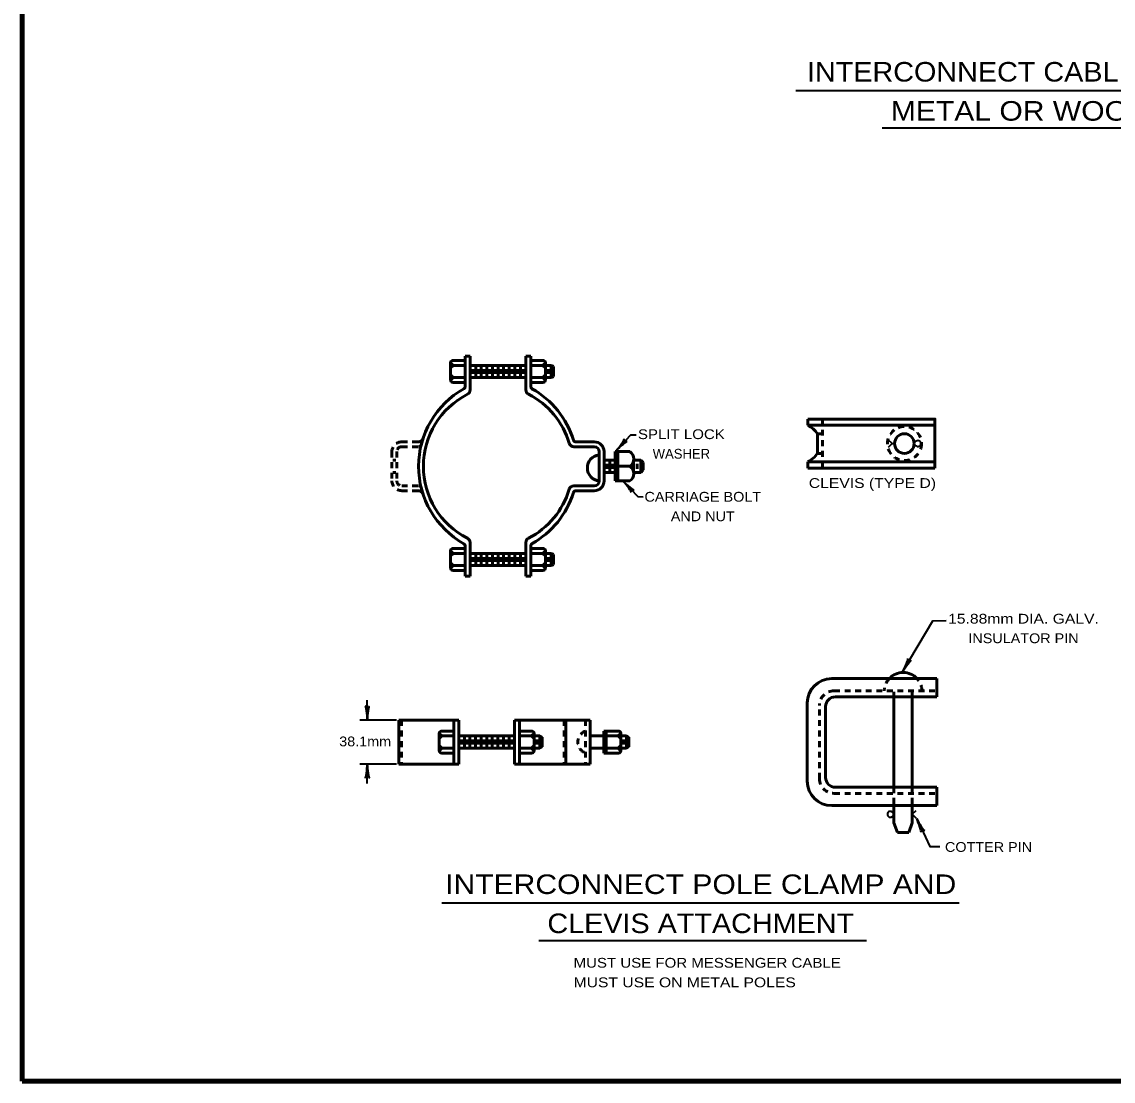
# Model space of a CAD drawing. Extents: x -421 to 434, y -46 to 498.
# Drawn here: x -364.1 to -96.1, y -34.2 to 225.9 of the extents above; entities that cross this region are included whole.
import ezdxf
from ezdxf.enums import TextEntityAlignment as Align

# ---------------------------------------------------------------- set-up
doc = ezdxf.new("R2010")
doc.units = 0
doc.header["$LTSCALE"] = 0.96
doc.linetypes.add('MEDIUM_DASHED', pattern=[4.5, 3, -1.5])
doc.linetypes.add('SHORT_DASHED', pattern=[2.7, 1.5, -1.2])
doc.layers.add('1', color=7, linetype='Continuous', lineweight=53)

msp = doc.modelspace()

# ---------------------------------------------------------------- linework, layer by layer
at = {"layer": '1', "lineweight": 40}
for p, q in [((-174.0904, 209.0297), (-37.3404, 209.0297)), ((-152.8823, 199.8058), (-57.4422, 199.8058)), ((-261.0137, 9.5761), (-133.9247, 9.5761)), ((-237.1632, 0.3522), (-156.753, 0.3522))]:
    msp.add_line(p, q, dxfattribs=at)
at = {"layer": '1'}
for p, q in [((-258.2165, 141.5306), (-258.8529, 142.167)), ((-258.8529, 142.1306), (-258.8529, 137.9306)), ((-258.2529, 142.7306), (-255.2529, 142.7306)), ((-255.2537, 136.3081), (-255.2537, 143.7531)), ((-255.2537, 143.7531), (-254.0537, 143.7531)), ((-254.0537, 135.5018), (-254.0537, 143.7531)), ((-240.3511, 135.5018), (-240.3511, 143.7531)), ((-240.3511, 143.7531), (-239.1511, 143.7531)), ((-239.1511, 136.3081), (-239.1511, 143.7531)), ((-236.1511, 142.7306), (-239.1511, 142.7306)), ((-236.1875, 141.5306), (-235.5511, 142.167)), ((-235.5511, 142.1306), (-235.5511, 137.9306)), ((-258.2165, 141.5306), (-258.8529, 140.8942)), ((-258.2165, 141.5306), (-255.2529, 141.5306)), ((-240.3511, 141.5306), (-254.0537, 141.5306)), ((-253.3685, 139.4306), (-253.3685, 140.6306)), ((-252.6833, 138.5306), (-252.6833, 141.5306)), ((-251.9981, 139.4306), (-251.9981, 140.6306)), ((-251.3129, 138.5306), (-251.3129, 141.5306)), ((-250.6277, 139.4306), (-250.6277, 140.6306)), ((-249.9425, 138.5306), (-249.9425, 141.5306)), ((-249.2573, 139.4306), (-249.2573, 140.6306)), ((-248.5721, 138.5306), (-248.5721, 141.5306)), ((-247.8869, 139.4306), (-247.8869, 140.6306)), ((-247.2017, 138.5306), (-247.2017, 141.5306)), ((-246.5165, 139.4306), (-246.5165, 140.6306)), ((-245.8313, 138.5306), (-245.8313, 141.5306)), ((-245.1461, 139.4306), (-245.1461, 140.6306)), ((-244.4609, 138.5306), (-244.4609, 141.5306)), ((-243.7757, 139.4306), (-243.7757, 140.6306)), ((-243.0905, 138.5306), (-243.0905, 141.5306)), ((-242.4053, 139.4306), (-242.4053, 140.6306)), ((-241.7201, 138.5306), (-241.7201, 141.5306)), ((-241.0349, 139.4306), (-241.0349, 140.6306)), ((-236.1875, 141.5306), (-239.1511, 141.5306)), ((-236.1875, 141.5306), (-235.5511, 140.8942)), ((-234.1807, 141.5306), (-235.5511, 141.5306)), ((-234.8708, 139.4306), (-234.8708, 140.6306)), ((-234.1807, 141.5306), (-234.1807, 138.5306)), ((-234.1807, 141.5306), (-233.5807, 141.2306)), ((-233.5807, 141.2306), (-233.5807, 138.8306)), ((-258.2165, 138.5306), (-258.8529, 139.167)), ((-258.2165, 138.5306), (-258.8529, 137.8942)), ((-258.2529, 137.3306), (-255.2529, 137.3306)), ((-258.2165, 138.5306), (-255.2529, 138.5306)), ((-240.3511, 138.5306), (-254.0537, 138.5306)), ((-236.1875, 138.5306), (-239.1511, 138.5306)), ((-236.1511, 137.3306), (-239.1511, 137.3306)), ((-236.1875, 138.5306), (-235.5511, 139.167)), ((-236.1875, 138.5306), (-235.5511, 137.8942)), ((-234.1807, 138.5306), (-235.5511, 138.5306)), ((-234.1807, 138.5306), (-233.5807, 138.8306)), ((-171.1344, 128.3214), (-171.1344, 126.8214)), ((-171.1344, 126.8214), (-139.9344, 126.8214)), ((-168.7344, 124.7214), (-168.7344, 119.9214)), ((-168.7344, 124.7214), (-167.5344, 124.7214)), ((-223.5511, 121.5531), (-228.5593, 121.5531)), ((-223.5511, 122.7531), (-228.0922, 122.7531)), ((-273.0137, 118.2531), (-272.2937, 118.2531)), ((-222.3511, 120.3531), (-222.3511, 113.1531)), ((-221.1511, 120.3531), (-221.1511, 113.1531)), ((-221.1511, 118.2531), (-218.4103, 118.2531)), ((-219.7807, 118.2531), (-219.7807, 115.2531)), ((-218.4103, 120.3531), (-218.4103, 113.1531)), ((-218.4103, 120.3531), (-214.8103, 120.3531)), ((-217.8103, 120.3531), (-217.8103, 113.1531)), ((-213.9008, 118.2531), (-212.1511, 118.2531)), ((-213.9008, 118.2531), (-213.9008, 115.2531)), ((-212.1511, 118.2531), (-212.1511, 115.2531)), ((-212.1511, 118.2531), (-211.5511, 117.6531)), ((-168.7344, 119.9214), (-167.5344, 119.9214)), ((-273.0137, 115.2531), (-272.2937, 115.2531)), ((-221.1511, 115.2531), (-218.4103, 115.2531)), ((-220.4659, 117.3531), (-220.4659, 116.1531)), ((-219.0955, 117.3531), (-219.0955, 116.1531)), ((-217.8103, 116.7531), (-214.8103, 116.7531)), ((-213.9008, 115.2531), (-212.1511, 115.2531)), ((-213.0297, 117.3531), (-213.0297, 116.1531)), ((-211.5511, 115.8531), (-212.1511, 115.2531)), ((-211.5511, 117.6531), (-211.5511, 115.8531)), ((-171.1344, 117.8214), (-139.9344, 117.8214)), ((-171.1344, 117.8214), (-171.1344, 116.3214)), ((-171.1344, 116.3214), (-139.9344, 116.3214)), ((-218.4103, 113.1531), (-214.8103, 113.1531)), ((-223.5511, 111.9531), (-228.5681, 111.9531)), ((-223.5511, 110.7531), (-228.1014, 110.7531)), ((-258.2529, 96.5787), (-255.2529, 96.5787)), ((-255.2537, 97.1981), (-255.2537, 89.7531)), ((-254.0537, 98.0044), (-254.0537, 89.7531)), ((-240.3511, 98.0342), (-240.3511, 89.7531)), ((-239.1511, 97.2344), (-239.1511, 89.7531)), ((-236.1511, 96.5787), (-239.1511, 96.5787)), ((-258.2165, 95.3787), (-258.8529, 96.0151)), ((-258.8529, 95.9787), (-258.8529, 91.7787)), ((-258.2165, 95.3787), (-258.8529, 94.7423)), ((-258.2165, 95.3787), (-255.2529, 95.3787)), ((-240.3511, 95.3787), (-254.0537, 95.3787)), ((-253.3685, 93.2787), (-253.3685, 94.4787)), ((-252.6833, 92.3787), (-252.6833, 95.3787)), ((-251.9981, 93.2787), (-251.9981, 94.4787)), ((-251.3129, 92.3787), (-251.3129, 95.3787)), ((-250.6277, 93.2787), (-250.6277, 94.4787)), ((-249.9425, 92.3787), (-249.9425, 95.3787)), ((-249.2573, 93.2787), (-249.2573, 94.4787)), ((-248.5721, 92.3787), (-248.5721, 95.3787)), ((-247.8869, 93.2787), (-247.8869, 94.4787)), ((-247.2017, 92.3787), (-247.2017, 95.3787)), ((-246.5165, 93.2787), (-246.5165, 94.4787)), ((-245.8313, 92.3787), (-245.8313, 95.3787)), ((-245.1461, 93.2787), (-245.1461, 94.4787)), ((-244.4609, 92.3787), (-244.4609, 95.3787)), ((-243.7757, 93.2787), (-243.7757, 94.4787)), ((-243.0905, 92.3787), (-243.0905, 95.3787)), ((-242.4053, 93.2787), (-242.4053, 94.4787)), ((-241.7201, 92.3787), (-241.7201, 95.3787)), ((-241.0349, 93.2787), (-241.0349, 94.4787)), ((-236.1875, 95.3787), (-239.1511, 95.3787)), ((-236.1875, 95.3787), (-235.5511, 96.0151)), ((-236.1875, 95.3787), (-235.5511, 94.7423)), ((-235.5511, 95.9787), (-235.5511, 91.7787)), ((-234.1807, 95.3787), (-235.5511, 95.3787)), ((-234.8708, 93.2787), (-234.8708, 94.4787)), ((-234.1807, 95.3787), (-234.1807, 92.3787)), ((-234.1807, 95.3787), (-233.5807, 95.0787)), ((-233.5807, 95.0787), (-233.5807, 92.6787)), ((-258.2165, 92.3787), (-258.8529, 93.0151)), ((-258.2165, 92.3787), (-258.8529, 91.7423)), ((-258.2529, 91.1787), (-255.2529, 91.1787)), ((-258.2165, 92.3787), (-255.2529, 92.3787)), ((-240.3511, 92.3787), (-254.0537, 92.3787)), ((-236.1875, 92.3787), (-239.1511, 92.3787)), ((-236.1511, 91.1787), (-239.1511, 91.1787)), ((-236.1875, 92.3787), (-235.5511, 93.0151)), ((-236.1875, 92.3787), (-235.5511, 91.7423)), ((-234.1807, 92.3787), (-235.5511, 92.3787)), ((-234.1807, 92.3787), (-233.5807, 92.6787)), ((-255.2537, 89.7531), (-254.0537, 89.7531)), ((-240.3511, 89.7531), (-239.1511, 89.7531)), ((-165.264, 64.647), (-139.464, 64.647)), ((-139.464, 64.647), (-139.464, 60.147)), ((-164.364, 60.147), (-139.464, 60.147)), ((-149.964, 60.147), (-149.964, 37.947)), ((-145.464, 60.147), (-145.464, 37.947)), ((-171.264, 39.447), (-171.264, 58.647)), ((-166.764, 40.347), (-166.764, 57.747)), ((-258.0362, 54.447), (-271.5362, 54.447)), ((-271.5362, 54.447), (-271.5362, 43.647)), ((-258.0362, 54.447), (-258.0362, 43.647)), ((-258.0362, 54.447), (-256.8362, 54.447)), ((-256.8362, 54.447), (-256.8362, 43.647)), ((-243.1344, 54.447), (-243.1344, 43.647)), ((-243.1344, 54.447), (-241.9344, 54.447)), ((-241.9344, 54.447), (-241.9344, 43.647)), ((-241.9344, 54.447), (-224.5344, 54.447)), ((-230.5344, 54.447), (-230.5344, 43.647)), ((-224.5344, 54.447), (-224.5344, 43.647)), ((-260.9998, 50.547), (-261.6362, 51.1834)), ((-261.6362, 51.147), (-261.6362, 46.947)), ((-261.0362, 51.747), (-258.0362, 51.747)), ((-238.9344, 51.747), (-241.9344, 51.747)), ((-238.9708, 50.547), (-238.3344, 51.1834)), ((-238.3344, 51.147), (-238.3344, 46.947)), ((-217.6344, 51.747), (-221.2344, 51.747)), ((-221.2344, 51.747), (-221.2344, 46.347)), ((-220.6344, 51.747), (-220.6344, 46.347)), ((-217.6708, 50.547), (-217.0344, 51.1834)), ((-217.0344, 51.147), (-217.0344, 46.947)), ((-260.9998, 50.547), (-261.6362, 49.9106)), ((-260.9998, 50.547), (-258.0362, 50.547)), ((-243.1344, 50.547), (-256.837, 50.547)), ((-256.1518, 48.447), (-256.1518, 49.647)), ((-255.4666, 47.547), (-255.4666, 50.547)), ((-254.7814, 48.447), (-254.7814, 49.647)), ((-254.0962, 47.547), (-254.0962, 50.547)), ((-253.411, 48.447), (-253.411, 49.647)), ((-252.7258, 47.547), (-252.7258, 50.547)), ((-252.0406, 48.447), (-252.0406, 49.647)), ((-251.3554, 47.547), (-251.3554, 50.547)), ((-250.6702, 48.447), (-250.6702, 49.647)), ((-249.985, 47.547), (-249.985, 50.547)), ((-249.2998, 48.447), (-249.2998, 49.647)), ((-248.6146, 47.547), (-248.6146, 50.547)), ((-247.9294, 48.447), (-247.9294, 49.647)), ((-247.2442, 47.547), (-247.2442, 50.547)), ((-246.559, 48.447), (-246.559, 49.647)), ((-245.8738, 47.547), (-245.8738, 50.547)), ((-245.1886, 48.447), (-245.1886, 49.647)), ((-244.5034, 47.547), (-244.5034, 50.547)), ((-243.8182, 48.447), (-243.8182, 49.647)), ((-238.9708, 50.547), (-241.9344, 50.547)), ((-238.9708, 50.547), (-238.3344, 49.9106)), ((-236.964, 50.547), (-238.3344, 50.547)), ((-237.6541, 48.447), (-237.6541, 49.647)), ((-236.964, 50.547), (-236.964, 47.547)), ((-236.964, 50.547), (-236.364, 50.247)), ((-236.364, 50.247), (-236.364, 47.847)), ((-224.5344, 50.547), (-221.2344, 50.547)), ((-217.6708, 50.547), (-220.6344, 50.547)), ((-217.6708, 50.547), (-217.0344, 49.9106)), ((-215.664, 50.547), (-217.0344, 50.547)), ((-216.3541, 48.447), (-216.3541, 49.647)), ((-215.664, 50.547), (-215.664, 47.547)), ((-215.664, 50.547), (-215.064, 50.247)), ((-215.064, 50.247), (-215.064, 47.847)), ((-260.9998, 47.547), (-261.6362, 48.1834)), ((-260.9998, 47.547), (-261.6362, 46.9106)), ((-261.0362, 46.347), (-258.0362, 46.347)), ((-260.9998, 47.547), (-258.0362, 47.547)), ((-243.1344, 47.547), (-256.837, 47.547)), ((-238.9708, 47.547), (-241.9344, 47.547)), ((-238.9344, 46.347), (-241.9344, 46.347)), ((-238.9708, 47.547), (-238.3344, 48.1834)), ((-238.9708, 47.547), (-238.3344, 46.9106)), ((-236.964, 47.547), (-238.3344, 47.547)), ((-236.964, 47.547), (-236.364, 47.847)), ((-224.5344, 47.547), (-221.2344, 47.547)), ((-217.6344, 46.347), (-221.2344, 46.347)), ((-217.6708, 47.547), (-220.6344, 47.547)), ((-217.6708, 47.547), (-217.0344, 48.1834)), ((-217.6708, 47.547), (-217.0344, 46.9106)), ((-215.664, 47.547), (-217.0344, 47.547)), ((-215.664, 47.547), (-215.064, 47.847)), ((-258.0362, 43.647), (-271.5362, 43.647)), ((-258.0362, 43.647), (-256.8362, 43.647)), ((-243.1344, 43.647), (-241.9344, 43.647)), ((-241.9344, 43.647), (-224.5344, 43.647)), ((-164.364, 37.947), (-139.464, 37.947)), ((-139.464, 37.947), (-139.464, 33.447)), ((-165.264, 33.447), (-139.464, 33.447)), ((-149.964, 33.447), (-149.964, 29.247)), ((-145.464, 33.447), (-145.464, 29.247)), ((-149.964, 29.247), (-149.124, 26.847)), ((-149.124, 26.847), (-146.304, 26.847)), ((-145.464, 29.247), (-146.304, 26.847))]:
    msp.add_line(p, q, dxfattribs=at)
at = {"layer": '1', "linetype": 'SHORT_DASHED'}
for p, q in [((-167.5344, 128.3214), (-167.5344, 116.3214)), ((-270.8537, 122.7531), (-266.7627, 122.7531)), ((-270.8537, 121.5531), (-266.6537, 121.5531)), ((-273.2537, 120.3531), (-273.2537, 113.1531)), ((-272.0537, 120.3531), (-272.0537, 113.1531)), ((-270.8537, 111.9531), (-266.6537, 111.9531)), ((-270.8537, 110.7531), (-266.7627, 110.7531)), ((-164.664, 61.647), (-139.464, 61.647)), ((-168.264, 40.047), (-168.264, 58.047)), ((-270.9362, 54.447), (-270.9362, 43.647)), ((-230.9263, 54.447), (-230.9263, 43.647)), ((-225.7344, 54.447), (-225.7344, 43.647)), ((-149.964, 37.947), (-149.964, 33.447)), ((-145.464, 37.947), (-145.464, 33.447)), ((-164.664, 36.447), (-139.464, 36.447))]:
    msp.add_line(p, q, dxfattribs=at)
at = {"layer": '1', "lineweight": 35}
for p, q in [((-150.41, 122.3214), (-151.3648, 123.276)), ((-150.41, 122.3214), (-151.3648, 121.3667)), ((-150.41, 122.3214), (-149.81, 122.3214)), ((-279.3022, 54.447), (-279.3022, 59.3104)), ((-272.1362, 54.447), (-281.1362, 54.447)), ((-272.1362, 43.647), (-281.1362, 43.647)), ((-279.3022, 38.847), (-279.3022, 43.647)), ((-145.464, 31.3174), (-144.5092, 32.272)), ((-145.464, 31.3174), (-144.5092, 30.3627))]:
    msp.add_line(p, q, dxfattribs=at)
at = {"layer": '1', "linetype": 'MEDIUM_DASHED'}
for p, q in [((-149.964, 60.147), (-149.964, 61.347)), ((-145.464, 60.147), (-145.464, 61.347))]:
    msp.add_line(p, q, dxfattribs=at)
at = {"layer": '1', "lineweight": 158}
msp.add_line((427.565, -34.2024), (-364.035, -34.2024), dxfattribs=at)
msp.add_lwpolyline([(427.565, 491.8976), (-364.135, 491.7976), (-364.035, -34.2024)], dxfattribs=at)
at = {"layer": '1'}
msp.add_lwpolyline([(-171.1344, 128.3214), (-139.9344, 128.3214), (-139.9344, 116.3214)], dxfattribs=at)
at = {"layer": '1', "lineweight": 35}
for points in [[(-218.1942, 120.6276), (-214.6063, 124.4411), (-213.2608, 124.4909)], [(-216.4749, 113.125), (-212.887, 109.3115), (-211.5415, 109.2617)], [(-147.8699, 66.2973), (-140.4548, 78.8187), (-137.1213, 78.8868)], [(-144.3865, 30.2542), (-141.1323, 23.4409), (-138.7106, 23.4409)]]:
    msp.add_lwpolyline(points, dxfattribs=at)
at = {"layer": '1', "linetype": 'SHORT_DASHED'}
msp.add_circle((-147.3882, 122.3262), 4.1803, dxfattribs=at)
at = {"layer": '1'}
msp.add_circle((-147.41, 122.3262), 2.4, dxfattribs=at)
for centre, radius, start, end in [((-258.2529, 142.1306), 0.6, 90, 180), ((-236.1511, 142.1306), 0.6, 0, 90), ((-258.2529, 137.9306), 0.6, 180, 270), ((-236.1511, 137.9306), 0.6, 270, 0), ((-244.9084, 116.7531), 21.8097, 119.23653, 240.76348), ((-245.6554, 116.7531), 19.8628, 117.10997, 242.89003), ((-255.8537, 136.3081), 0.6, 299.23653, 0), ((-255.2537, 135.5018), 1.2, 297.10997, 0), ((-239.1511, 135.5018), 1.2, 180, 242.89003), ((-248.7494, 116.7531), 19.8628, 16.5506, 62.89003), ((-238.5511, 136.3081), 0.6, 180, 240.76347), ((-249.508, 116.7531), 21.8097, 17.12844, 60.76347), ((-173.8305, 121.3187), 6.1277, 33.73114, 63.89701), ((-228.5593, 122.7531), 1.2, 196.5506, 270), ((-228.0922, 123.3531), 0.6, 197.12844, 270), ((-223.5511, 120.3531), 2.4, 0, 90), ((-223.5511, 120.3531), 1.2, 0, 90), ((-222.0431, 116.3506), 3.2123, 96.73046, 264.49836), ((-216.0873, 118.5531), 2.2069, 305.35262, 54.64738), ((-173.8305, 123.3573), 6.1277, 296.10299, 326.26886), ((-216.0873, 114.9531), 2.2069, 305.35262, 54.64738), ((-223.5511, 113.1531), 2.4, 270, 0), ((-223.5511, 113.1531), 1.2, 270, 0), ((-248.7494, 116.7829), 19.8628, 297.10997, 343.36481), ((-249.508, 116.7829), 21.8097, 299.27052, 342.79181), ((-228.5681, 110.7531), 1.2, 90, 163.36481), ((-228.1014, 110.1531), 0.6, 90, 162.79181), ((-258.2529, 95.9787), 0.6, 90, 180), ((-255.8537, 97.1981), 0.6, 0, 60.76347), ((-255.2537, 98.0044), 1.2, 0, 62.89003), ((-239.1511, 98.0342), 1.2, 117.10997, 180), ((-238.5511, 97.2344), 0.6, 119.27052, 180), ((-236.1511, 95.9787), 0.6, 0, 90), ((-258.2529, 91.7787), 0.6, 180, 270), ((-236.1511, 91.7787), 0.6, 270, 0), ((-165.264, 58.647), 6, 90, 180), ((-147.714, 61.4614), 4.6537, 43.15014, 136.90375), ((-164.364, 57.747), 2.4, 90, 180), ((-261.0362, 51.147), 0.6, 90, 180), ((-238.9344, 51.147), 0.6, 0, 90), ((-217.6344, 51.147), 0.6, 0, 90), ((-261.0362, 46.947), 0.6, 180, 270), ((-238.9344, 46.947), 0.6, 270, 0), ((-217.6344, 46.947), 0.6, 270, 0), ((-164.364, 40.347), 2.4, 180, 270), ((-165.264, 39.447), 6, 180, 270)]:
    msp.add_arc(centre, radius, start, end, dxfattribs=at)
at = {"layer": '1', "linetype": 'SHORT_DASHED'}
for centre, radius, start, end in [((-266.7627, 123.9531), 1.2, 270, 341.76525), ((-270.8537, 120.3531), 2.4, 90, 180), ((-270.8537, 120.3531), 1.2, 90, 180), ((-266.6537, 122.1531), 0.6, 270, 0), ((-270.8537, 113.1531), 2.4, 180, 270), ((-270.8537, 113.1531), 1.2, 180, 270), ((-266.7627, 109.5375), 1.2, 18.23475, 90), ((-266.6537, 111.3531), 0.6, 0, 90), ((-147.714, 61.4614), 4.6537, 136.80174, 177.71462), ((-147.714, 61.4614), 4.6537, 2.28538, 43.19826), ((-164.664, 58.047), 3.6, 90, 180), ((-224.7204, 49.047), 2.8841, 110.5841, 249.4159), ((-164.664, 40.047), 3.6, 180, 270)]:
    msp.add_arc(centre, radius, start, end, dxfattribs=at)
at = {"layer": '1', "lineweight": 35}
for centre, radius, start, end in [((-143.8716, 121.8376), 1.2608, 108.38064, 151.10471), ((-143.8776, 122.8306), 1.252, 208.73791, 251.77673), ((-144.0851, 122.3377), 0.7203, 255.19279, 104.80721), ((-150.8602, 31.3147), 0.7203, 75.19279, 284.80721), ((-151.0677, 31.8076), 1.252, 288.22327, 331.26209), ((-151.0737, 30.8146), 1.2608, 28.89529, 71.61936)]:
    msp.add_arc(centre, radius, start, end, dxfattribs=at)
at = {"layer": '1', "lineweight": 40}
for centre, major_axis, ratio, start_param, end_param in [((-217.5384, 121.8085), (-1.3319, -1.6891), 0.122415, 0.89635335, 3.14159265), ((-217.5384, 121.8085), (-1.3319, -1.6891), 0.122415, 0.89635335, 3.14159265), ((-217.0879, 121.4329), (1.5978, 1.3907), 0.07063, 6.28230741, 8.55970261), ((-217.0879, 121.4329), (1.5978, 1.3907), 0.07063, 6.28230741, 8.55970261), ((-215.7385, 111.9717), (-1.2908, 1.6795), 0.07063, 3.14071475, 5.41810995), ((-215.3361, 112.3985), (-1.6048, 1.4323), 0.122415, 0.89635335, 3.14159265), ((-147.488, 67.5929), (-0.9307, -1.9393), 0.122415, 0.89635335, 3.14159265), ((-146.9663, 67.3249), (-1.2554, -1.7062), 0.07063, 3.14071475, 5.41810995), ((-279.6338, 55.7564), (0.1874, -2.1428), 0.122415, 0.89635335, 3.14159265), ((-279.6338, 55.7564), (0.1874, -2.1428), 0.122415, 0.89635335, 3.14159265), ((-279.0483, 55.7916), (-0.2108, -2.1077), 0.07063, 3.14071475, 5.41810995), ((-279.0483, 55.7916), (-0.2108, -2.1077), 0.07063, 3.14071475, 5.41810995), ((-279.5561, 42.3024), (0.2108, 2.1077), 0.07063, 3.14071475, 5.41810995), ((-279.5561, 42.3024), (0.2108, 2.1077), 0.07063, 3.14071475, 5.41810995), ((-278.9706, 42.3376), (-0.1874, 2.1428), 0.122415, 0.89635335, 3.14159265), ((-278.9706, 42.3376), (-0.1874, 2.1428), 0.122415, 0.89635335, 3.14159265), ((-144.0361, 28.9315), (0.7182, -1.9928), 0.07063, 6.28230741, 8.55970261), ((-143.523, 29.2155), (-1.0926, 1.8528), 0.122415, 0.89635335, 3.14159265)]:
    msp.add_ellipse(centre, major_axis=major_axis, ratio=ratio, start_param=start_param, end_param=end_param, dxfattribs=at)

# ---------------------------------------------------------------- texts
at = {"layer": '1'}
for s, height, width, p in [('INTERCONNECT CABLE ATTACHMENT', 4.8, 1.1, (-105.6255, 211.1991)), ('METAL OR WOOD POLES', 4.8, 1.15, (-105.6254, 201.5991)), ('SPLIT LOCK', 2.4, 1.15, (-202.1732, 123.4226)), ('CLEVIS (TYPE D)', 2.4, 1.2, (-155.2579, 111.433)), ('CARRIAGE BOLT', 2.4, 1.1, (-196.9178, 108.0632)), ('AND NUT', 2.4, 1.1, (-196.9178, 103.2632)), ('15.88mm DIA. GALV.', 2.4, 1.2, (-118.1624, 78.1282)), ('INSULATOR PIN', 2.4, 1.1, (-118.1623, 73.3282)), ('38.1mm', 2.4, 1.1, (-279.8238, 47.9999)), ('COTTER PIN', 2.4, 1.1, (-126.7535, 22.0895)), ('INTERCONNECT POLE CLAMP AND', 4.8, 1.15, (-197.4173, 11.7455)), ('CLEVIS ATTACHMENT', 4.8, 1.1, (-197.4172, 2.1455))]:
    msp.add_text(s, height=height, dxfattribs=dict(at, width=width)).set_placement(p, align=Align.CENTER)
msp.add_text('WASHER', height=2.4, dxfattribs=at).set_placement((-202.1731, 118.6226), align=Align.CENTER)
for s, width, p in [('MUST USE FOR MESSENGER CABLE', 1.15, (-228.6452, -6.3432)), ('MUST USE ON METAL POLES', 1.2, (-228.6452, -11.1432))]:
    msp.add_text(s, height=2.4, dxfattribs=dict(at, width=width)).set_placement(p)

doc.saveas('drawing.dxf')
